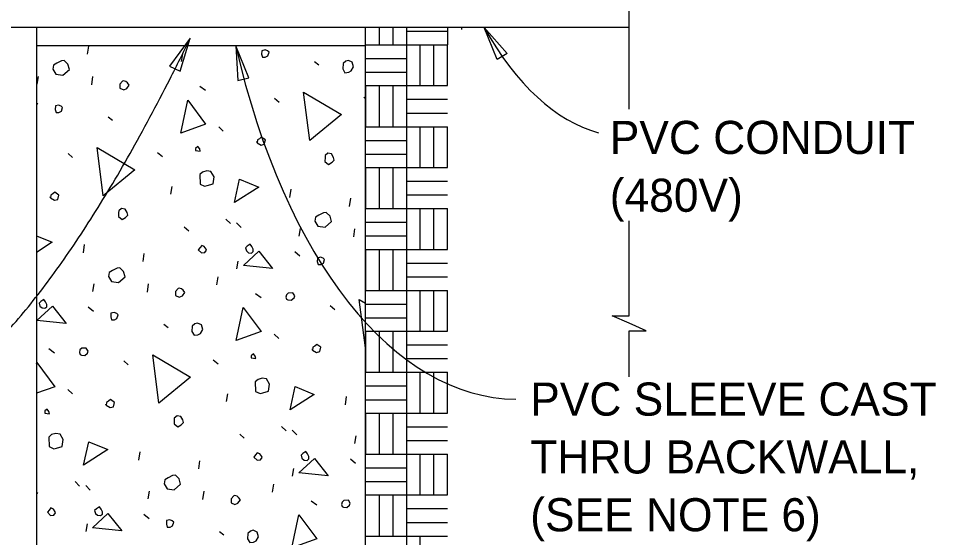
# Model space of a CAD drawing. Extents: x -1660015.2 to -1659984.9, y 2580594.2 to 2580616.7.
# Drawn here: x -1659989.055 to -1659984.871, y 2580599.906 to 2580602.277 of the extents above; entities that cross this region are included whole.
import ezdxf

# ---------------------------------------------------------------- set-up
doc = ezdxf.new("R2010")
doc.units = 0
for name, color, linetype in [('Default', 7, 'Continuous'), ('Miscellaneous', 7, 'Continuous'), ('Miscellaneous3', 7, 'Continuous'), ('SheetLines_dp', 7, 'Continuous')]:
    doc.layers.add(name, color=color, linetype=linetype)

msp = doc.modelspace()

# ---------------------------------------------------------------- linework, layer by layer
at = {"layer": 'Default'}
msp.add_line((-1659986.2685, 2580602.2354), (-1659989.3273, 2580602.2354), dxfattribs=at)
at = {"layer": 'Miscellaneous'}
for p, q in [((-1659987.4094, 2580602.2354), (-1659987.4094, 2580602.156)), ((-1659987.3469, 2580602.2354), (-1659987.3469, 2580602.156)), ((-1659987.2832, 2580602.156), (-1659987.2832, 2580602.2354)), ((-1659987.2832, 2580602.2185), (-1659987.0969, 2580602.2185)), ((-1659987.0969, 2580602.2354), (-1659987.0969, 2580602.156)), ((-1659987.0344, 2580602.2354), (-1659987.0344, 2580602.2264)), ((-1659987.472, 2580602.1521), (-1659988.972, 2580602.1521)), ((-1659988.7399, 2580602.1128), (-1659988.7344, 2580602.1505)), ((-1659987.4719, 2580602.156), (-1659987.2832, 2580602.156)), ((-1659987.2832, 2580601.7822), (-1659987.2832, 2580602.156)), ((-1659987.2832, 2580602.156), (-1659987.0969, 2580602.156)), ((-1659987.2219, 2580601.9697), (-1659987.2219, 2580602.156)), ((-1659987.1594, 2580601.9697), (-1659987.1594, 2580602.156)), ((-1659987.0969, 2580601.9697), (-1659987.0969, 2580602.156)), ((-1659988.3118, 2580602.08), (-1659988.3057, 2580602.1153)), ((-1659987.7036, 2580602.0799), (-1659987.6839, 2580602.0645)), ((-1659987.4719, 2580602.0935), (-1659987.2832, 2580602.0935)), ((-1659988.9698, 2580601.9761), (-1659988.9638, 2580602.0114)), ((-1659988.7205, 2580601.9731), (-1659988.7151, 2580602.0108)), ((-1659987.4719, 2580602.031), (-1659987.2832, 2580602.031)), ((-1659988.2274, 2580601.968), (-1659988.2016, 2580601.949)), ((-1659987.4719, 2580601.9697), (-1659987.0969, 2580601.9697)), ((-1659987.4719, 2580601.9697), (-1659987.4719, 2580601.7822)), ((-1659987.4094, 2580601.9697), (-1659987.4094, 2580601.7822)), ((-1659987.3469, 2580601.9697), (-1659987.3469, 2580601.7822)), ((-1659987.8863, 2580601.9119), (-1659987.866, 2580601.8941)), ((-1659987.4789, 2580601.9175), (-1659987.472, 2580601.9118)), ((-1659988.972, 2580601.891), (-1659988.9665, 2580601.8865)), ((-1659987.2832, 2580601.9072), (-1659987.0969, 2580601.9072)), ((-1659988.6453, 2580601.8276), (-1659988.6257, 2580601.8121)), ((-1659987.2832, 2580601.8447), (-1659987.0969, 2580601.8447)), ((-1659988.1412, 2580601.7815), (-1659988.1203, 2580601.7612)), ((-1659987.4719, 2580601.7822), (-1659987.2832, 2580601.7822)), ((-1659987.2832, 2580601.7822), (-1659987.0969, 2580601.7822)), ((-1659987.2832, 2580601.4085), (-1659987.2832, 2580601.7822)), ((-1659987.2219, 2580601.596), (-1659987.2219, 2580601.7822)), ((-1659987.1594, 2580601.596), (-1659987.1594, 2580601.7822)), ((-1659987.0969, 2580601.596), (-1659987.0969, 2580601.7822)), ((-1659987.4719, 2580601.7197), (-1659987.2832, 2580601.7197)), ((-1659988.8281, 2580601.6596), (-1659988.8078, 2580601.6417)), ((-1659988.4206, 2580601.6652), (-1659988.3973, 2580601.6456)), ((-1659987.4719, 2580601.6572), (-1659987.2832, 2580601.6572)), ((-1659987.4719, 2580601.596), (-1659987.0969, 2580601.596)), ((-1659987.4719, 2580601.596), (-1659987.4719, 2580601.4085)), ((-1659987.4094, 2580601.596), (-1659987.4094, 2580601.4085)), ((-1659987.3469, 2580601.596), (-1659987.3469, 2580601.4085)), ((-1659987.2832, 2580601.5335), (-1659987.0969, 2580601.5335)), ((-1659988.3592, 2580601.4746), (-1659988.3531, 2580601.5099)), ((-1659987.8168, 2580601.4595), (-1659987.8114, 2580601.4972)), ((-1659987.5445, 2580601.4186), (-1659987.539, 2580601.4563)), ((-1659987.2832, 2580601.471), (-1659987.0969, 2580601.471)), ((-1659987.4719, 2580601.4084), (-1659987.2832, 2580601.4084)), ((-1659987.2832, 2580601.4085), (-1659987.0969, 2580601.4085)), ((-1659987.2832, 2580601.0346), (-1659987.2832, 2580601.4084)), ((-1659987.2219, 2580601.2221), (-1659987.2219, 2580601.4084)), ((-1659987.1594, 2580601.2221), (-1659987.1594, 2580601.4084)), ((-1659987.0969, 2580601.2221), (-1659987.0969, 2580601.4084)), ((-1659988.2985, 2580601.3252), (-1659988.2782, 2580601.3074)), ((-1659988.1087, 2580601.3606), (-1659988.0877, 2580601.3403)), ((-1659988.0599, 2580601.3426), (-1659988.0389, 2580601.3223)), ((-1659987.4719, 2580601.3459), (-1659987.2832, 2580601.3459)), ((-1659987.7744, 2580601.2819), (-1659987.7683, 2580601.3172)), ((-1659987.5251, 2580601.2788), (-1659987.5197, 2580601.3165)), ((-1659987.4719, 2580601.2834), (-1659987.2832, 2580601.2834)), ((-1659988.7586, 2580601.2071), (-1659988.7532, 2580601.2448)), ((-1659988.4862, 2580601.1662), (-1659988.4808, 2580601.2039)), ((-1659987.7945, 2580601.2118), (-1659987.7711, 2580601.1922)), ((-1659987.4719, 2580601.2221), (-1659987.0969, 2580601.2221)), ((-1659987.4719, 2580601.2221), (-1659987.4719, 2580601.0346)), ((-1659987.4094, 2580601.2221), (-1659987.4094, 2580601.0346)), ((-1659987.3469, 2580601.2221), (-1659987.3469, 2580601.0346)), ((-1659988.0582, 2580601.1334), (-1659988.0521, 2580601.1687)), ((-1659987.2832, 2580601.1596), (-1659987.0969, 2580601.1596)), ((-1659988.1497, 2580601.0597), (-1659988.1443, 2580601.0974)), ((-1659987.2832, 2580601.0971), (-1659987.0969, 2580601.0971)), ((-1659988.7162, 2580601.0295), (-1659988.7101, 2580601.0648)), ((-1659988.4669, 2580601.0265), (-1659988.4615, 2580601.0641)), ((-1659987.4719, 2580601.0346), (-1659987.2832, 2580601.0346)), ((-1659987.2832, 2580600.6609), (-1659987.2832, 2580601.0346)), ((-1659987.2832, 2580601.0346), (-1659987.0969, 2580601.0346)), ((-1659987.2219, 2580600.8484), (-1659987.2219, 2580601.0346)), ((-1659987.1594, 2580600.8484), (-1659987.1594, 2580601.0346)), ((-1659987.0969, 2580600.8484), (-1659987.0969, 2580601.0346)), ((-1659987.9738, 2580601.0214), (-1659987.948, 2580601.0024)), ((-1659988.7362, 2580600.9595), (-1659988.7129, 2580600.9398)), ((-1659987.6326, 2580600.9653), (-1659987.6123, 2580600.9474)), ((-1659987.4719, 2580600.9721), (-1659987.2832, 2580600.9721)), ((-1659987.4719, 2580600.9096), (-1659987.2832, 2580600.9096)), ((-1659988.3917, 2580600.881), (-1659988.372, 2580600.8655)), ((-1659987.8876, 2580600.8349), (-1659987.8666, 2580600.8146)), ((-1659987.4719, 2580600.8484), (-1659987.0969, 2580600.8484)), ((-1659987.4719, 2580600.8484), (-1659987.4719, 2580600.6609)), ((-1659987.4094, 2580600.8484), (-1659987.4094, 2580600.6609)), ((-1659987.3469, 2580600.8484), (-1659987.3469, 2580600.6609)), ((-1659987.2832, 2580600.7859), (-1659987.0969, 2580600.7859)), ((-1659988.9156, 2580600.7691), (-1659988.8898, 2580600.7501)), ((-1659988.5744, 2580600.7129), (-1659988.5541, 2580600.6951)), ((-1659988.167, 2580600.7186), (-1659988.1436, 2580600.699)), ((-1659987.2832, 2580600.7234), (-1659987.0969, 2580600.7234)), ((-1659987.4719, 2580600.6609), (-1659987.2832, 2580600.6609)), ((-1659987.2832, 2580600.2871), (-1659987.2832, 2580600.6609)), ((-1659987.2832, 2580600.6609), (-1659987.0969, 2580600.6609)), ((-1659987.2219, 2580600.4746), (-1659987.2219, 2580600.6609)), ((-1659987.1594, 2580600.4746), (-1659987.1594, 2580600.6609)), ((-1659987.0969, 2580600.4746), (-1659987.0969, 2580600.6609)), ((-1659988.8294, 2580600.5825), (-1659988.8084, 2580600.5623)), ((-1659987.4719, 2580600.5984), (-1659987.2832, 2580600.5984)), ((-1659988.1056, 2580600.528), (-1659988.0995, 2580600.5633)), ((-1659987.5632, 2580600.5129), (-1659987.5578, 2580600.5505)), ((-1659987.4719, 2580600.5359), (-1659987.2832, 2580600.5359)), ((-1659987.4719, 2580600.4746), (-1659987.0969, 2580600.4746)), ((-1659987.4719, 2580600.4746), (-1659987.4719, 2580600.2871)), ((-1659987.4094, 2580600.4746), (-1659987.4094, 2580600.2871)), ((-1659987.3469, 2580600.4746), (-1659987.3469, 2580600.2871)), ((-1659987.855, 2580600.414), (-1659987.8341, 2580600.3937)), ((-1659987.2832, 2580600.4121), (-1659987.0969, 2580600.4121)), ((-1659988.0448, 2580600.3786), (-1659988.0245, 2580600.3608)), ((-1659987.8062, 2580600.396), (-1659987.7853, 2580600.3757)), ((-1659987.5208, 2580600.3353), (-1659987.5147, 2580600.3706)), ((-1659987.2832, 2580600.3496), (-1659987.0969, 2580600.3496)), ((-1659988.505, 2580600.2605), (-1659988.4995, 2580600.2982)), ((-1659987.4719, 2580600.2871), (-1659987.2832, 2580600.2871)), ((-1659987.2832, 2580600.2871), (-1659987.0969, 2580600.2871)), ((-1659987.2832, 2580599.9134), (-1659987.2832, 2580600.2871)), ((-1659987.2219, 2580600.1009), (-1659987.2219, 2580600.2871)), ((-1659987.1594, 2580600.1009), (-1659987.1594, 2580600.2871)), ((-1659987.0969, 2580600.1009), (-1659987.0969, 2580600.2871)), ((-1659988.2326, 2580600.2196), (-1659988.2272, 2580600.2573)), ((-1659987.5408, 2580600.2652), (-1659987.5174, 2580600.2456)), ((-1659987.8045, 2580600.1868), (-1659987.7984, 2580600.2221)), ((-1659987.4719, 2580600.2246), (-1659987.2832, 2580600.2246)), ((-1659988.7968, 2580600.1616), (-1659988.7758, 2580600.1413)), ((-1659987.4719, 2580600.1621), (-1659987.2832, 2580600.1621)), ((-1659988.972, 2580600.1134), (-1659988.9663, 2580600.1084)), ((-1659988.748, 2580600.1436), (-1659988.727, 2580600.1234)), ((-1659988.4626, 2580600.0829), (-1659988.4565, 2580600.1182)), ((-1659988.2133, 2580600.0799), (-1659988.2078, 2580600.1175)), ((-1659987.8961, 2580600.1131), (-1659987.8906, 2580600.1508)), ((-1659987.7202, 2580600.0748), (-1659987.6944, 2580600.0558)), ((-1659987.4719, 2580600.1009), (-1659987.0969, 2580600.1009)), ((-1659987.4094, 2580600.1009), (-1659987.4094, 2580599.9134)), ((-1659987.3469, 2580600.1009), (-1659987.3469, 2580599.9134)), ((-1659987.2832, 2580600.0384), (-1659987.0969, 2580600.0384)), ((-1659988.4826, 2580600.0129), (-1659988.4592, 2580599.9932)), ((-1659988.7463, 2580599.9344), (-1659988.7402, 2580599.9697)), ((-1659987.2832, 2580599.9759), (-1659987.0969, 2580599.9759)), ((-1659988.138, 2580599.9344), (-1659988.1184, 2580599.9189)), ((-1659987.4719, 2580599.9134), (-1659987.2832, 2580599.9134)), ((-1659987.2832, 2580599.9134), (-1659987.0969, 2580599.9134)), ((-1659987.2832, 2580599.5396), (-1659987.2832, 2580599.9134)), ((-1659987.2219, 2580599.7271), (-1659987.2219, 2580599.9134))]:
    msp.add_line(p, q, dxfattribs=at)
for points in [[(-1659987.9455, 2580602.1135), (-1659987.9416, 2580602.099), (-1659987.9289, 2580602.0998), (-1659987.9174, 2580602.1054), (-1659987.9117, 2580602.1225), (-1659987.9184, 2580602.1285), (-1659987.93, 2580602.1331), (-1659987.9445, 2580602.1292), (-1659987.9455, 2580602.1135)], [(-1659988.8976, 2580602.0447), (-1659988.8839, 2580602.0225), (-1659988.8517, 2580602.0182), (-1659988.8224, 2580602.0441), (-1659988.8289, 2580602.0683), (-1659988.8461, 2580602.0844), (-1659988.8589, 2580602.0835), (-1659988.8793, 2580602.0729), (-1659988.8949, 2580602.0635), (-1659988.8976, 2580602.0447)], [(-1659987.5742, 2580602.0706), (-1659987.5756, 2580602.0469), (-1659987.5656, 2580602.0289), (-1659987.5481, 2580602.031), (-1659987.5367, 2580602.0366), (-1659987.5261, 2580602.055), (-1659987.5319, 2580602.0767), (-1659987.5496, 2580602.0849), (-1659987.5617, 2580602.0817), (-1659987.5742, 2580602.0706)], [(-1659988.592, 2580601.9764), (-1659988.5923, 2580601.9582), (-1659988.5746, 2580601.9501), (-1659988.5608, 2580601.9563), (-1659988.5495, 2580601.9723), (-1659988.5576, 2580601.9831), (-1659988.5644, 2580601.989), (-1659988.5753, 2580601.9913), (-1659988.5801, 2580601.99), (-1659988.592, 2580601.9764)], [(-1659987.726, 2580601.7193), (-1659987.7539, 2580601.9396), (-1659987.5818, 2580601.8382), (-1659987.726, 2580601.7193)], [(-1659988.8872, 2580601.8611), (-1659988.8834, 2580601.8466), (-1659988.8706, 2580601.8474), (-1659988.8592, 2580601.8531), (-1659988.8534, 2580601.8702), (-1659988.8602, 2580601.8761), (-1659988.8718, 2580601.8808), (-1659988.8863, 2580601.8769), (-1659988.8872, 2580601.8611)], [(-1659988.3148, 2580601.7531), (-1659988.2828, 2580601.904), (-1659988.2015, 2580601.7938), (-1659988.3148, 2580601.7531)], [(-1659987.9666, 2580601.7092), (-1659987.9482, 2580601.6986), (-1659987.9337, 2580601.7025), (-1659987.9286, 2580601.722), (-1659987.9476, 2580601.735), (-1659987.956, 2580601.7276), (-1659987.965, 2580601.7226), (-1659987.9666, 2580601.7092), (-1659987.9679, 2580601.714)], [(-1659988.6678, 2580601.467), (-1659988.6957, 2580601.6873), (-1659988.5236, 2580601.5858), (-1659988.6678, 2580601.467)], [(-1659988.2467, 2580601.673), (-1659988.2255, 2580601.6709), (-1659988.2281, 2580601.6806), (-1659988.2361, 2580601.6913), (-1659988.2469, 2580601.6833), (-1659988.2467, 2580601.673)], [(-1659987.6562, 2580601.6423), (-1659987.6565, 2580601.6241), (-1659987.6399, 2580601.6104), (-1659987.6243, 2580601.6198), (-1659987.6141, 2580601.6302), (-1659987.6174, 2580601.6423), (-1659987.6267, 2580601.6579), (-1659987.6431, 2580601.6613), (-1659987.6557, 2580601.6502), (-1659987.6562, 2580601.6423)], [(-1659988.2279, 2580601.5641), (-1659988.2266, 2580601.5205), (-1659988.2058, 2580601.5105), (-1659988.1937, 2580601.5138), (-1659988.1672, 2580601.5209), (-1659988.1628, 2580601.5531), (-1659988.1772, 2580601.5777), (-1659988.1961, 2580601.5804), (-1659988.2154, 2580601.5753), (-1659988.2279, 2580601.5641)], [(-1659988.0693, 2580601.4358), (-1659988.0462, 2580601.5429), (-1659987.9589, 2580601.5068), (-1659988.0693, 2580601.4358)], [(-1659988.9083, 2580601.4569), (-1659988.89, 2580601.4463), (-1659988.8755, 2580601.4501), (-1659988.8704, 2580601.4696), (-1659988.8894, 2580601.4827), (-1659988.8977, 2580601.4752), (-1659988.9068, 2580601.4702), (-1659988.9083, 2580601.4569), (-1659988.9096, 2580601.4617)], [(-1659988.5979, 2580601.3899), (-1659988.5982, 2580601.3717), (-1659988.5816, 2580601.3581), (-1659988.566, 2580601.3674), (-1659988.5559, 2580601.3779), (-1659988.5591, 2580601.39), (-1659988.5685, 2580601.4056), (-1659988.5849, 2580601.4089), (-1659988.5975, 2580601.3978), (-1659988.5979, 2580601.3899)], [(-1659987.7022, 2580601.3504), (-1659987.6885, 2580601.3282), (-1659987.6563, 2580601.3239), (-1659987.627, 2580601.3499), (-1659987.6335, 2580601.374), (-1659987.6507, 2580601.3901), (-1659987.6634, 2580601.3893), (-1659987.6839, 2580601.3786), (-1659987.6995, 2580601.3693), (-1659987.7022, 2580601.3504)], [(-1659988.972, 2580601.2839), (-1659988.9007, 2580601.2545), (-1659988.972, 2580601.2086)], [(-1659988.2343, 2580601.2208), (-1659988.2201, 2580601.2065), (-1659988.2049, 2580601.2079), (-1659988.1972, 2580601.2178), (-1659988.1985, 2580601.2226), (-1659988.2072, 2580601.2358), (-1659988.2188, 2580601.2405), (-1659988.2266, 2580601.2306), (-1659988.2343, 2580601.2208)], [(-1659988.0153, 2580601.2148), (-1659988.0054, 2580601.2071), (-1659987.9921, 2580601.2055), (-1659987.9837, 2580601.2129), (-1659987.9839, 2580601.2232), (-1659987.9895, 2580601.2346), (-1659987.9976, 2580601.2454), (-1659988.0108, 2580601.2367), (-1659988.0191, 2580601.2293), (-1659988.0153, 2580601.2148)], [(-1659988.0287, 2580601.1491), (-1659987.9582, 2580601.2145), (-1659987.8957, 2580601.1355), (-1659988.0287, 2580601.1491)], [(-1659987.6918, 2580601.1668), (-1659987.6879, 2580601.1524), (-1659987.6752, 2580601.1532), (-1659987.6638, 2580601.1588), (-1659987.658, 2580601.1759), (-1659987.6648, 2580601.1819), (-1659987.6764, 2580601.1865), (-1659987.6909, 2580601.1826), (-1659987.6918, 2580601.1668)], [(-1659988.644, 2580601.0981), (-1659988.6303, 2580601.0759), (-1659988.598, 2580601.0716), (-1659988.5688, 2580601.0975), (-1659988.5752, 2580601.1217), (-1659988.5925, 2580601.1377), (-1659988.6052, 2580601.1369), (-1659988.6256, 2580601.1263), (-1659988.6413, 2580601.1169), (-1659988.644, 2580601.0981)], [(-1659988.3384, 2580601.0298), (-1659988.3387, 2580601.0116), (-1659988.321, 2580601.0034), (-1659988.3071, 2580601.0097), (-1659988.2959, 2580601.0257), (-1659988.3039, 2580601.0365), (-1659988.3107, 2580601.0424), (-1659988.3217, 2580601.0447), (-1659988.3265, 2580601.0434), (-1659988.3384, 2580601.0298)], [(-1659988.957, 2580600.9624), (-1659988.9472, 2580600.9547), (-1659988.9338, 2580600.9531), (-1659988.9255, 2580600.9605), (-1659988.9256, 2580600.9708), (-1659988.9313, 2580600.9823), (-1659988.9394, 2580600.993), (-1659988.9525, 2580600.9843), (-1659988.9609, 2580600.9769), (-1659988.957, 2580600.9624)], [(-1659987.832, 2580600.9947), (-1659987.8259, 2580600.9912), (-1659987.8101, 2580600.9902), (-1659987.7976, 2580601.0013), (-1659987.7947, 2580601.0099), (-1659987.8034, 2580601.0231), (-1659987.824, 2580601.0227), (-1659987.8324, 2580601.0153), (-1659987.8346, 2580601.0043), (-1659987.832, 2580600.9947)], [(-1659987.4723, 2580600.7727), (-1659987.5003, 2580600.993), (-1659987.472, 2580600.9763)], [(-1659988.9705, 2580600.8967), (-1659988.9, 2580600.9622), (-1659988.8374, 2580600.8832), (-1659988.9705, 2580600.8967)], [(-1659988.0611, 2580600.8065), (-1659988.0291, 2580600.9574), (-1659987.9478, 2580600.8472), (-1659988.0611, 2580600.8065)], [(-1659988.6336, 2580600.9145), (-1659988.6297, 2580600.9), (-1659988.617, 2580600.9008), (-1659988.6056, 2580600.9065), (-1659988.5998, 2580600.9236), (-1659988.6066, 2580600.9295), (-1659988.6182, 2580600.9342), (-1659988.6327, 2580600.9303), (-1659988.6336, 2580600.9145)], [(-1659988.2624, 2580600.8716), (-1659988.2638, 2580600.8479), (-1659988.2538, 2580600.8299), (-1659988.2362, 2580600.832), (-1659988.2248, 2580600.8377), (-1659988.2142, 2580600.8561), (-1659988.22, 2580600.8778), (-1659988.2377, 2580600.886), (-1659988.2498, 2580600.8827), (-1659988.2624, 2580600.8716)], [(-1659987.7129, 2580600.7626), (-1659987.6946, 2580600.752), (-1659987.6801, 2580600.7559), (-1659987.6749, 2580600.7754), (-1659987.694, 2580600.7884), (-1659987.7023, 2580600.781), (-1659987.7113, 2580600.776), (-1659987.7129, 2580600.7626), (-1659987.7142, 2580600.7674)], [(-1659988.7738, 2580600.7423), (-1659988.7677, 2580600.7388), (-1659988.7519, 2580600.7379), (-1659988.7394, 2580600.749), (-1659988.7365, 2580600.7575), (-1659988.7452, 2580600.7707), (-1659988.7658, 2580600.7704), (-1659988.7742, 2580600.763), (-1659988.7764, 2580600.752), (-1659988.7738, 2580600.7423)], [(-1659988.4141, 2580600.5204), (-1659988.4421, 2580600.7406), (-1659988.27, 2580600.6392), (-1659988.4141, 2580600.5204)], [(-1659987.9931, 2580600.7264), (-1659987.9718, 2580600.7243), (-1659987.9744, 2580600.734), (-1659987.9825, 2580600.7447), (-1659987.9933, 2580600.7367), (-1659987.9931, 2580600.7264)], [(-1659987.472, 2580600.773), (-1659987.4723, 2580600.7727)], [(-1659988.972, 2580600.6999), (-1659988.9709, 2580600.7051), (-1659988.8896, 2580600.5949), (-1659988.972, 2580600.5652)], [(-1659987.9743, 2580600.6175), (-1659987.9729, 2580600.5739), (-1659987.9522, 2580600.5639), (-1659987.9401, 2580600.5672), (-1659987.9135, 2580600.5743), (-1659987.9092, 2580600.6065), (-1659987.9236, 2580600.6311), (-1659987.9424, 2580600.6338), (-1659987.9617, 2580600.6287), (-1659987.9743, 2580600.6175)], [(-1659987.8157, 2580600.4892), (-1659987.7926, 2580600.5963), (-1659987.7053, 2580600.5602), (-1659987.8157, 2580600.4892)], [(-1659988.6547, 2580600.5103), (-1659988.6363, 2580600.4997), (-1659988.6218, 2580600.5035), (-1659988.6167, 2580600.523), (-1659988.6357, 2580600.5361), (-1659988.6441, 2580600.5286), (-1659988.6531, 2580600.5236), (-1659988.6547, 2580600.5103), (-1659988.656, 2580600.5151)], [(-1659988.9349, 2580600.474), (-1659988.9136, 2580600.4719), (-1659988.9162, 2580600.4816), (-1659988.9243, 2580600.4924), (-1659988.935, 2580600.4843), (-1659988.9349, 2580600.474)], [(-1659988.3443, 2580600.4433), (-1659988.3446, 2580600.4251), (-1659988.328, 2580600.4115), (-1659988.3124, 2580600.4208), (-1659988.3023, 2580600.4313), (-1659988.3055, 2580600.4434), (-1659988.3148, 2580600.459), (-1659988.3313, 2580600.4623), (-1659988.3438, 2580600.4512), (-1659988.3443, 2580600.4433)], [(-1659988.9161, 2580600.3652), (-1659988.9147, 2580600.3215), (-1659988.8939, 2580600.3116), (-1659988.8819, 2580600.3148), (-1659988.8553, 2580600.3219), (-1659988.851, 2580600.3541), (-1659988.8653, 2580600.3788), (-1659988.8842, 2580600.3815), (-1659988.9035, 2580600.3763), (-1659988.9161, 2580600.3652)], [(-1659988.7574, 2580600.2369), (-1659988.7344, 2580600.344), (-1659988.6471, 2580600.3078), (-1659988.7574, 2580600.2369)], [(-1659987.9806, 2580600.2742), (-1659987.9664, 2580600.2599), (-1659987.9513, 2580600.2613), (-1659987.9436, 2580600.2712), (-1659987.9449, 2580600.276), (-1659987.9536, 2580600.2892), (-1659987.9652, 2580600.2938), (-1659987.9729, 2580600.284), (-1659987.9806, 2580600.2742)], [(-1659987.7616, 2580600.2682), (-1659987.7518, 2580600.2604), (-1659987.7384, 2580600.2589), (-1659987.73, 2580600.2663), (-1659987.7302, 2580600.2766), (-1659987.7359, 2580600.288), (-1659987.7439, 2580600.2988), (-1659987.7571, 2580600.2901), (-1659987.7655, 2580600.2827), (-1659987.7616, 2580600.2682)], [(-1659987.7751, 2580600.2024), (-1659987.7046, 2580600.2679), (-1659987.642, 2580600.1889), (-1659987.7751, 2580600.2024)], [(-1659988.3903, 2580600.1515), (-1659988.3766, 2580600.1293), (-1659988.3444, 2580600.1249), (-1659988.3151, 2580600.1509), (-1659988.3216, 2580600.1751), (-1659988.3388, 2580600.1911), (-1659988.3516, 2580600.1903), (-1659988.372, 2580600.1797), (-1659988.3876, 2580600.1703), (-1659988.3903, 2580600.1515)], [(-1659988.0848, 2580600.0832), (-1659988.0851, 2580600.065), (-1659988.0673, 2580600.0568), (-1659988.0535, 2580600.0631), (-1659988.0422, 2580600.0791), (-1659988.0503, 2580600.0899), (-1659988.0571, 2580600.0958), (-1659988.068, 2580600.0981), (-1659988.0729, 2580600.0968), (-1659988.0848, 2580600.0832)], [(-1659987.5784, 2580600.0481), (-1659987.5723, 2580600.0445), (-1659987.5565, 2580600.0436), (-1659987.544, 2580600.0547), (-1659987.5411, 2580600.0633), (-1659987.5498, 2580600.0765), (-1659987.5704, 2580600.0761), (-1659987.5788, 2580600.0687), (-1659987.581, 2580600.0577), (-1659987.5784, 2580600.0481)], [(-1659988.9224, 2580600.0218), (-1659988.9082, 2580600.0075), (-1659988.8931, 2580600.009), (-1659988.8854, 2580600.0188), (-1659988.8867, 2580600.0236), (-1659988.8954, 2580600.0368), (-1659988.907, 2580600.0415), (-1659988.9147, 2580600.0317), (-1659988.9224, 2580600.0218)], [(-1659988.7034, 2580600.0158), (-1659988.6936, 2580600.0081), (-1659988.6802, 2580600.0065), (-1659988.6718, 2580600.0139), (-1659988.672, 2580600.0242), (-1659988.6776, 2580600.0357), (-1659988.6857, 2580600.0464), (-1659988.6989, 2580600.0377), (-1659988.7073, 2580600.0303), (-1659988.7034, 2580600.0158)], [(-1659988.7168, 2580599.9501), (-1659988.6464, 2580600.0156), (-1659988.5838, 2580599.9366), (-1659988.7168, 2580599.9501)], [(-1659988.38, 2580599.9679), (-1659988.3761, 2580599.9534), (-1659988.3634, 2580599.9542), (-1659988.3519, 2580599.9599), (-1659988.3462, 2580599.9769), (-1659988.3529, 2580599.9829), (-1659988.3645, 2580599.9876), (-1659988.379, 2580599.9837), (-1659988.38, 2580599.9679)], [(-1659987.8075, 2580599.8599), (-1659987.7755, 2580600.0108), (-1659987.6942, 2580599.9006), (-1659987.8075, 2580599.8599)], [(-1659988.0087, 2580599.925), (-1659988.0101, 2580599.9013), (-1659988.0001, 2580599.8833), (-1659987.9826, 2580599.8854), (-1659987.9712, 2580599.8911), (-1659987.9605, 2580599.9095), (-1659987.9664, 2580599.9312), (-1659987.9841, 2580599.9394), (-1659987.9962, 2580599.9361), (-1659988.0087, 2580599.925)]]:
    msp.add_lwpolyline(points, dxfattribs=at)
at = {"layer": 'Miscellaneous3'}
for p, q in [((-1659988.972, 2580602.2354), (-1659988.972, 2580597.7672)), ((-1659987.472, 2580597.7672), (-1659987.472, 2580602.2354))]:
    msp.add_line(p, q, dxfattribs=at)
at = {"layer": 'SheetLines_dp'}
for points in [[(-1659986.2685, 2580601.863), (-1659986.2685, 2580604.1496)], [(-1659986.2685, 2580600.6396), (-1659986.2685, 2580600.8508), (-1659986.191, 2580600.8508), (-1659986.2685, 2580600.8846), (-1659986.346, 2580600.9183), (-1659986.2685, 2580600.9183), (-1659986.2685, 2580601.3522)]]:
    msp.add_lwpolyline(points, dxfattribs=at)
for points in [[(-1659986.9306, 2580602.2354), (-1659986.8259, 2580602.1164), (-1659986.8709, 2580602.0886)], [(-1659988.2709, 2580602.1865), (-1659988.3651, 2580602.0591), (-1659988.3179, 2580602.0352)], [(-1659988.0639, 2580602.152), (-1659988.0548, 2580601.9939), (-1659988.0032, 2580602.0057)]]:
    msp.add_lwpolyline(points, close=True, dxfattribs=at)
for centre, major_axis, ratio, start_param, end_param in [((-1659986.1854, 2580604.1042), (0.1111, 2.3674), 0.464296, 2.502126, 3.038691), ((-1659986.762, 2580603.3018), (0.0241, 2.7636), 0.515084, 2.004362, 3.141607)]:
    msp.add_ellipse(centre, major_axis=major_axis, ratio=ratio, start_param=start_param, end_param=end_param, dxfattribs=at)
msp.add_open_spline([(-1659990.7679, 2580600.2937), (-1659989.7598, 2580600.2551), (-1659988.8041, 2580601.0904), (-1659988.2709, 2580602.1865)], degree=2, dxfattribs=at)

# ---------------------------------------------------------------- texts
for s, p in [('PVC CONDUIT', (-1659986.3574, 2580601.6577)), ('(480V)', (-1659986.3574, 2580601.3937)), ('PVC SLEEVE CAST', (-1659986.7203, 2580600.463)), ('THRU BACKWALL,', (-1659986.7203, 2580600.199)), ('(SEE NOTE 6)', (-1659986.7203, 2580599.935))]:
    msp.add_text(s, height=0.1512, dxfattribs=at).set_placement(p)

doc.saveas('drawing.dxf')
